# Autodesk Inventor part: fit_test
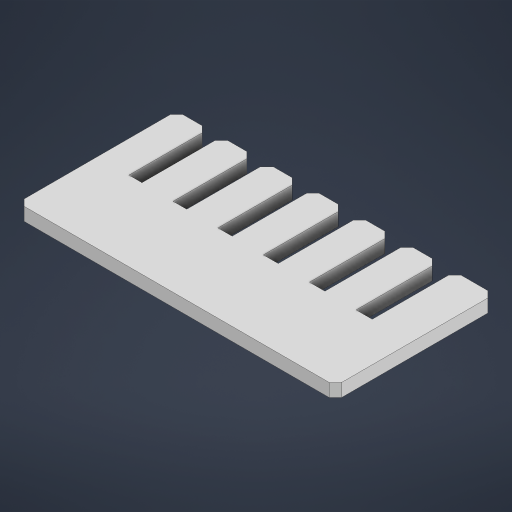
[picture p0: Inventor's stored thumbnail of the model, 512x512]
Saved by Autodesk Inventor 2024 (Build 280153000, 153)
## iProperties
Created: 2023-09
Part Number: fit_test
Material: Generic
Document SubType Name: Modeling
Designer: mammothbane
Density: 1 g/cm^3
Appearance: Default
Author: mammothbane
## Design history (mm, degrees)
sketch "Sketch1"
  geometry: L1 (0, 0)-(-100, 0); L2 (-100, 0)-(-100, -50); L3 (-100, -50)-(0, -50); L4 (0, -50)-(0, 0)
  constraints: 8 end point, 2 parallel, 1 horizontal, 1 perpendicular
  dimensions: "width" = 50 distance of L1.end L2.end; "length" = 100 distance of L1.start L1.end
extrude "Extrusion1" new body sketch "Sketch1" taper "d3" = 0 deg; distance "cardboard_thickness" = 4.1
sketch "Sketch2"
  geometry: L1 (10, 50)-(14.1, 50); L2 (14.1, 50)-(14.1, 25); L3 (14.1, 25)-(10, 25); L4 (10, 25)-(10, 50); L5 (0, 50)-(0, 0) reference; L6 (24.1, 50)-(28.4, 50); L7 (28.4, 50)-(28.4, 24.8); L8 (28.4, 24.8)-(24.1, 24.8); L9 (24.1, 24.8)-(24.1, 50); L10 (38.4, 50)-(42.9, 50); L11 (42.9, 50)-(42.9, 24.6); L12 (42.9, 24.6)-(38.4, 24.6); L13 (38.4, 24.6)-(38.4, 50); L14 (52.9, 50)-(57.6, 50); L15 (57.6, 50)-(57.6, 24.4); L16 (57.6, 24.4)-(52.9, 24.4); L17 (52.9, 24.4)-(52.9, 50); L18 (67.6, 50)-(72.5, 50); L19 (72.5, 50)-(72.5, 24.2); L20 (72.5, 24.2)-(67.6, 24.2); L21 (67.6, 24.2)-(67.6, 50); L22 (73.239, 50)-(80.557, 50); L23 (82.5, 50)-(87.6, 50); L24 (87.6, 50)-(87.6, 24); L25 (87.6, 24)-(82.5, 24); L26 (82.5, 24)-(82.5, 50); 8 further points
  constraints: 50 end point, 12 parallel, 7 horizontal, 6 perpendicular, 1 midpoint, 8 other
  dimensions: "slot_height" = 25 distance of L1.end L2.end; "slot_width" = 4.1 distance of L2.end L3.end (= cardboard_thickness); "d6" = 10 distance from line of point (10, 37.5) L5; "d12" = 10 distance between parallel lines of L2 L9; "d13" = 4.3 distance between parallel lines of L7 L9 (= cardboard_thickness + kerf_increment); "d14" = 25.2 dimension on L8 (= slot_height + kerf_increment); "d15" = 10 distance between parallel lines of L17 L11; "d16" = 10 distance between parallel lines of L21 L15; "d17" = 25.8 distance of L18.end L19.end (= slot_height + 4 x kerf_increment); "d18" = 4.5 distance of L11.end L12.end (= cardboard_thickness + 2 x kerf_increment); "d19" = 25.4 distance of L10.end L11.end (= slot_height + 2 x kerf_increment); "d20" = 10 distance between parallel lines of L7 L13; "d21" = 4.7 distance of L15.end L16.end (= cardboard_thickness + 3 x kerf_increment); "d22" = 25.6 distance of L14.end L15.end (= slot_height + 3 x kerf_increment); "d23" = 4.9 distance of L19.end L20.end (= cardboard_thickness + 4 x kerf_increment); "d24" = 10 distance between parallel lines of L26 L19; "d25" = 5.1 distance of L24.end L25.end (= cardboard_thickness + 5 x kerf_increment); "d26" = 26 distance of L23.end L24.end (= slot_height + 5 x kerf_increment)
extrude "Extrusion2" cut sketch "Sketch2" stored distance "d7" = 4; taper "d8" = 0 deg
chamfer "Chamfer1" distance "d27" = 2; stored, may be unused: second distance "d28" = 2, angle "d29" = 45 deg
body "Solid1"
other parameters: "kerf_increment" = 0.2 [user parameter; used in 10 equation terms]
